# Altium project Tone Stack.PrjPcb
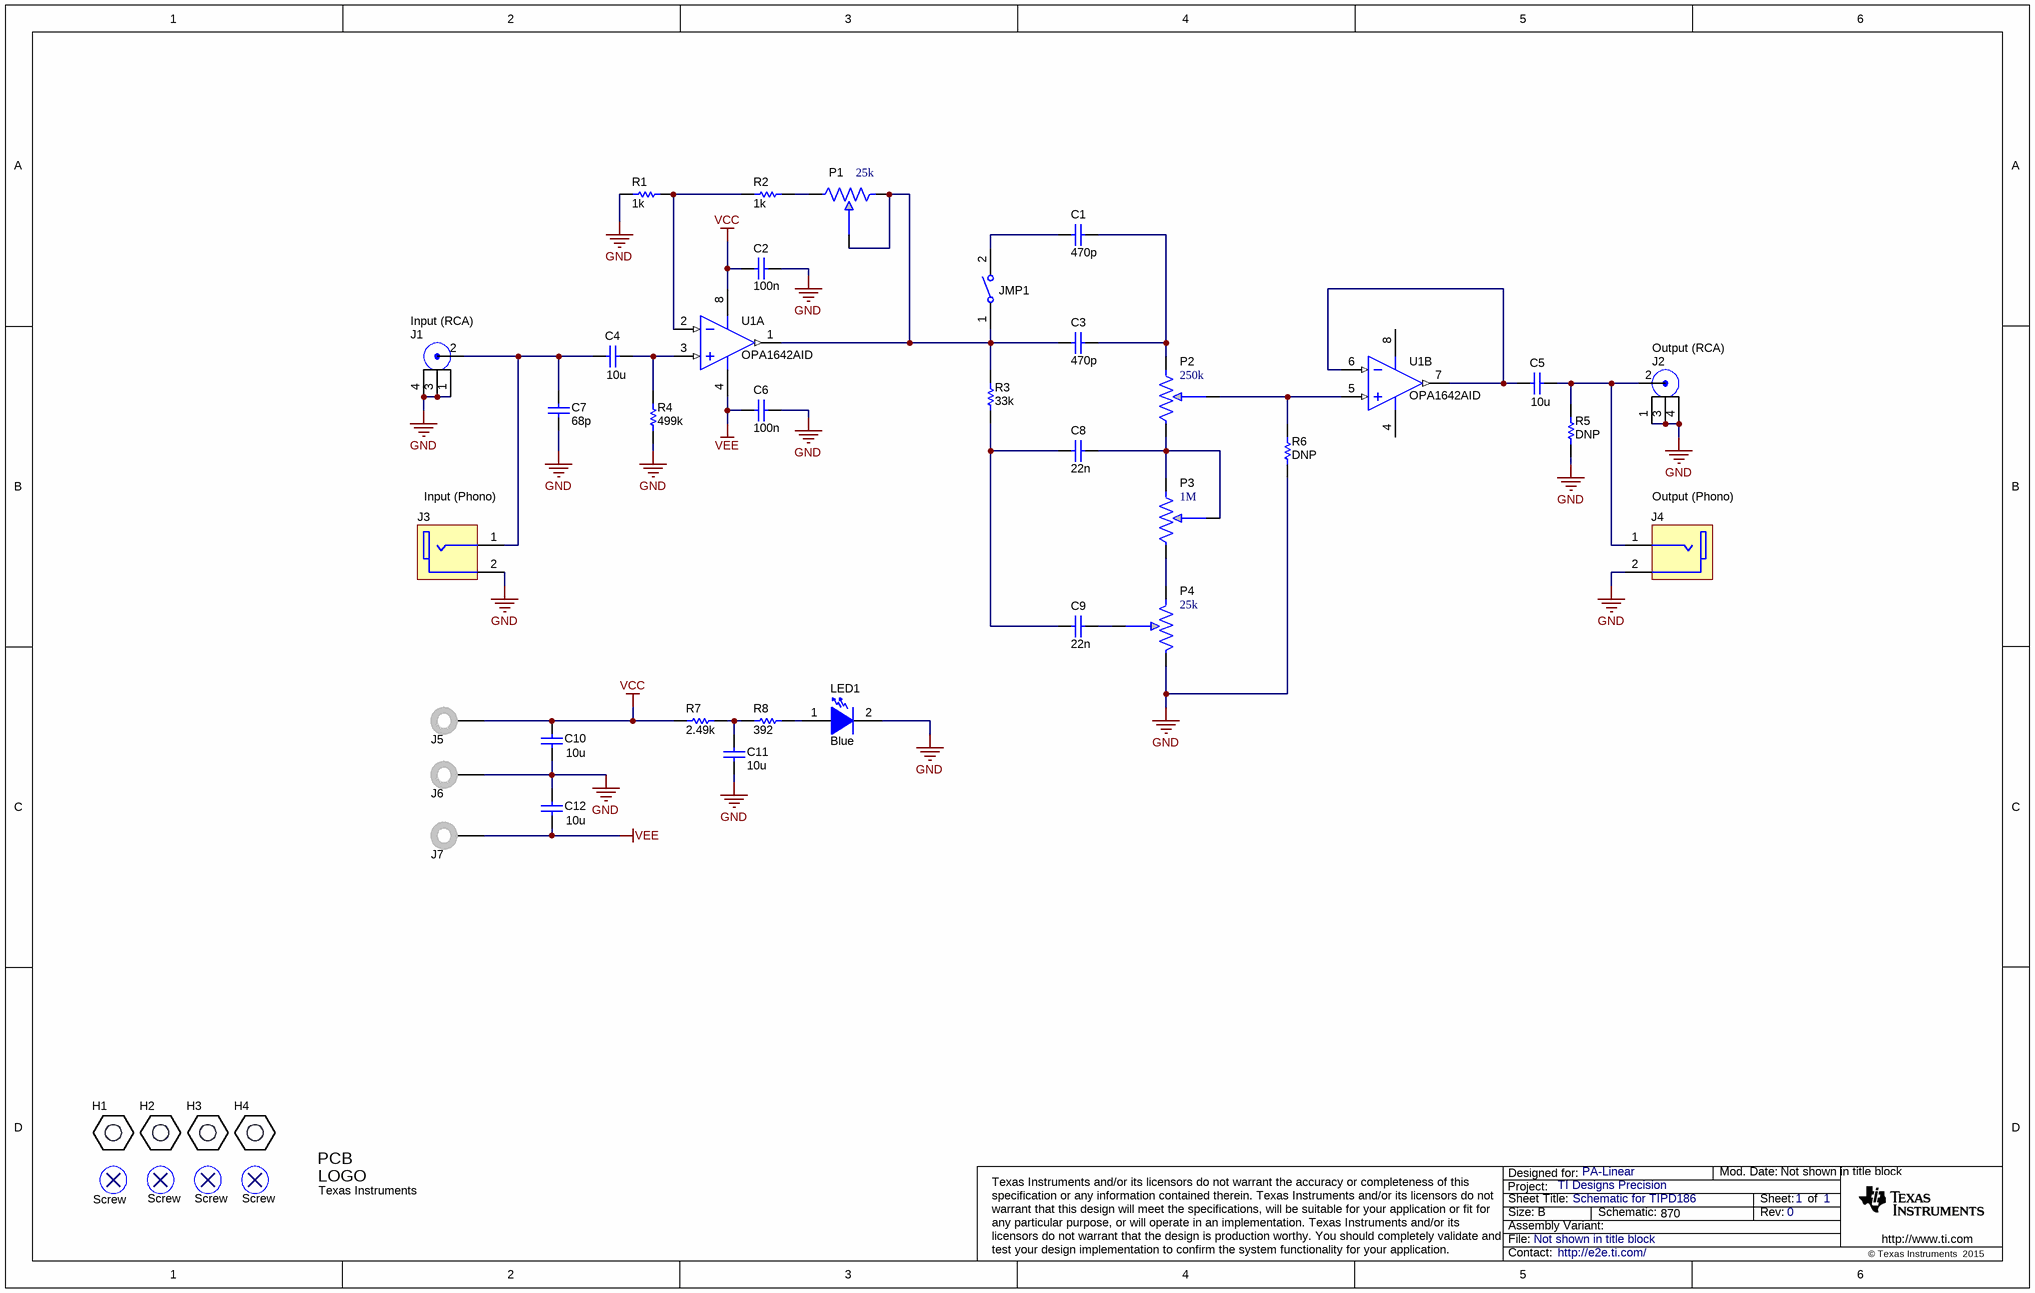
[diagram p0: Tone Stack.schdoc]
TechSupport: http://e2e.ti.com/; SCH_Rev: 0; PRJ_Title: TI Designs Precision; PRJ_Customer: PA-Linear; CopyrightYear: 2015
1 sheet, 43 parts. Net scope: global (net labels, ports and power ports of the same name join across sheets).
Board file: Tone Stack.PcbDoc

## Sheet Tone Stack.schdoc: Schematic for TIPD186
size B; Date: Not shown in title block; ApprovedBy: Not shown in title block; CheckedBy: Not shown in title block; Author: Not shown in title block; CompanyName: Not shown in title block; DrawnBy: Not shown in title block; Engineer: Not shown in title block; Organization: Not shown in title block; Address1: Not shown in title block; Address2: Not shown in title block; Address3: Not shown in title block; Address4: Not shown in title block; DocumentNumber: 1; Revision: Use project parameter SCH_Rev; SheetNumber: 1; SheetTotal: 1; PageSetup: Record=PageOptions|CenterHorizontal=True|CenterVertical=True|PrintScale=0.72|XCorrection=1.00|YCorrection=1.00|PrintKind=0|BorderSize=5000000|LeftOffset=0|BottomOffset=0|Orientation=2|PaperLength=1000|PaperWidth=1000|Scale=100|PaperSource=15|PrintQuality=600|MediaType=1|DitherType=10|PaperKind=Letter|PrintScaleMode=1

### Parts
C1  value 470p  [0603]  (hidden comment: Used in BOM report)
C2  value 100n  [0603]  (hidden comment: Used in BOM report)
C3  value 470p  [0603]  (hidden comment: Used in BOM report)
C4  value 10u  [1206]  (hidden comment: Used in BOM report)
C5  value 10u  [1206]  (hidden comment: Used in BOM report)
C6  value 100n  [0603]  (hidden comment: Used in BOM report)
C7  value 68p  [0603]  (hidden comment: Used in BOM report)
C8  value 22n  [1206]  (hidden comment: Used in BOM report)
C9  value 22n  [1206]  (hidden comment: Used in BOM report)
C10  value 10u  [1206]  (hidden comment: Used in BOM report)
C11  value 10u  [1206]  (hidden comment: Used in BOM report)
C12  value 10u  [1206]  (hidden comment: Used in BOM report)
H1  Standoff, 1", 4-40, Alum, F-F  [STANDOFF HEX 4-40THR ALUM 1"L]  (value not drawn)
H2  Standoff, 1", 4-40, Alum, F-F  [STANDOFF HEX 4-40THR ALUM 1"L]  (value not drawn)
H3  Standoff, 1", 4-40, Alum, F-F  [STANDOFF HEX 4-40THR ALUM 1"L]  (value not drawn)
H4  Standoff, 1", 4-40, Alum, F-F  [STANDOFF HEX 4-40THR ALUM 1"L]  (value not drawn)
J1  Input (RCA)  [RCJ-01X]
J2  Output (RCA)  [RCJ-01X]
J3  Input (Phono)  [Switchcraft_RN111PC]
J4  Output (Phono)  [Switchcraft_RN111PC]
J5  VCC  [JACK NON-INSULATED .218"]  (value not drawn)
J6  GND  [JACK NON-INSULATED .218"]  (value not drawn)
J7  Vee  [JACK NON-INSULATED .218"]  (value not drawn)
JMP1  Mid Boost  [Header 100mil, 1x2]  (value not drawn)
LED1  value Blue  [Header 100mil, 1x2]  (hidden comment: XREBLU-L1-R250-00K01)
Logo1  Texas Instruments  [TI_Stacked_Overlay_Medium]  (no BOM)
P1  value 25k  [POT_RV16]  (hidden comment: Gain)
P2  value 250k  [POT_RV16]  (hidden comment: Treble)
P3  value 1M  [POT_RV16]  (hidden comment: Bass)
P4  value 25k  [POT_RV16]  (hidden comment: Mid)
R1  value 1k  [0603]  (hidden comment: Used in BOM report)
R2  value 1k  [0603]  (hidden comment: Used in BOM report)
R3  value 33k  [0603]  (hidden comment: Used in BOM report)
R4  value 499k  [0603]  (hidden comment: Used in BOM report)
R5  value DNP  [0603]  (hidden comment: Used in BOM report)
R6  value DNP  [0603]  (hidden comment: Used in BOM report)
R7  value 2.49k  [0805]  (hidden comment: Used in BOM report)
R8  value 392  [0805]  (hidden comment: Used in BOM report)
U1  OPA1642AID  [D0008A_N]  (parts A,B of 2)
U2  Screw  (mechanical)
U3  Screw  (mechanical)
U4  Screw  (mechanical)
U5  Screw  (mechanical)

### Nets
GND: C2.2 C6.2 C7.2 C10.2 C11.2 C12.1 J1.1 J1.3 J1.4 J2.1 J2.3 J2.4 J3.2(Tip) J4.2(Tip) J6.1 LED1.2(K) P4.1 R1.2 R4.2 R5.1 R6.1
VCC: C2.1 C10.1 J5.1 R7.1 U1.8(V+)
VEE: C6.1 C12.2 J7.1 U1.4(V-)
NetC1_1: C1.1 JMP1.2
NetC1_2: C1.2 C3.2 P2.3
NetC3_1: C3.1 JMP1.1 P1.2 P1.3 R3.2 U1.1(OUT_A)
NetC4_1: C4.1 R4.1 U1.3(IN_A+)
NetC4_2: C4.2 C7.1 J1.2 J3.1(Sleeve)
NetC5_1: C5.1 J2.2 J4.1(Sleeve) R5.2
NetC5_2: C5.2 U1.6(IN_B-) U1.7(OUT_B)
NetC8_1: C8.1 C9.1 R3.1
NetC8_2: C8.2 P2.1 P3.2 P3.3
NetC9_2: C9.2 P4.2
NetC11_1: C11.1 R7.2 R8.1
NetLED1_1: LED1.1(A) R8.2
NetP1_1: P1.1 R2.1
NetP2_2: P2.2 R6.2 U1.5(IN_B+)
NetP3_1: P3.1 P4.3
NetR1_1: R1.1 R2.2 U1.2(IN_A-)

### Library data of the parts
C1-C12 = Capacitor: CAP, CERM, xxxF, xxV, [TempCo], xx%, [PackageReference]; Polarized: N; U/M: EA
H1-H4 = Standoff, 1", 4-40, Alum, F-F: STANDOFF HEX 4-40THR ALUM 1"L; Manufacturer: Keystone; PartNumber: 2205; SymbolVersion: use current date i.e. 2008-05-20; SymbolCreator: Use LDAP id; CompType: Used in some BOM reports.  Useful for finding later.; U/M: EA, IN, or GM
J1 J2 = RCJ-011: RCA Jack, Metal, Right Angle; Manufacturer: CUI Inc; SymbolVersion: use current date i.e. 2008-05-20; SymbolCreator: Use LDAP id; CompType: Used in some BOM reports.  Useful for finding later.; U/M: EA, IN, or GM
J3 J4 = RN111PC: Phone Jack, 1/4", R/A, TH; Manufacturer: Switchcraft; SymbolCreator: a0411947; CompType: AUDIO JACK; U/M: EA
J5-J7 = Banana Jack, Solder: JACK NON-INSULATED .218"; Manufacturer: Keystone; PartNumber: 575-4; SymbolVersion: use current date i.e. 2008-05-20; SymbolCreator: Use LDAP id; CompType: Used in some BOM reports.  Useful for finding later.; U/M: EA, IN, or GM
JMP1 = CHS-01TB: Switch, Slide, SPST, Top Slide, SMT; Manufacturer: Copal Electronics; SymbolCreator: a0799628; VDC_V: 6; SwitchFunction: Off-On; PositionCount: 1; CurrentRating_mA: 100
LED1 = XREBLU-L1-R250-00K01: LED, Blue, SMD; Manufacturer: Cree; Type: InGaN; Vf_V: 3.3; Value2: 3.3V; Io_A: 0.35; RJC_CperW: 8; Tjmax_C: 150; Power_TotalModule: 1.155; Value1: 1.155W; LambdaD: 470; NumParallelLEDs: 1; LuminousFlux_PhiV: 30.6; Angle: 90; FamilyName: XLamp&#174; XR-E; U/M: EA
Logo1 = TI_Logo: Texas Instrument Corporate Signature; SymbolCreator: a0412235
P1-P4 = POT_CT-9WXXXYYY: Potentiometer, Single Slide,  xxOhms, 0.1W, 20%; Manufacturer: Copal; Area: 100,776
R1-R8 = Resistor: RES, xxx ohm, x%, xW, [PackageReference]; U/M: EA
U1 = OPA1652AID: Sound Plus Low Noise and Distortion, General-Purpose, FET-Input Audio Operational Amplifier, 4.5 to 36 V, -40 to 85 degC, 8-pin SOIC (D0008A), Green (RoHS & no Sb/Br); Manufacturer: Texas Instruments; Alternate Manufacturer: None; Alternate PartNumber: Equivalent; CMRR(Min)(dB): 100; GBW(Typ)(MHz): 18; Iq per channel(Max)(mA): 2.5; Number of Channels: 2; Packing: TUBE; Rating: Catalog; Slew Rate(Typ)(V/us): 10; Sub Family: Audio Operational Amplifier, High Supply Voltage Amplifier (>=30V), Low Noise Amp (<=10nV/rtHz), Precision Amplifier; Total Supply Voltage(Max)(+5V is 5, +/-5V is 10): 36; Total Supply Voltage(Min)(+5V is 5, +/-5V is 10): 4.5; Vio (25C)(Max)(mV): 1.5
U2-U5 = Machine Screw, 4-40, 0.25": MACHINE SCREW PAN PHILLIPS 4-40; Manufacturer: B&F Fastener Supply; PartNumber: PMSSS 440 0025 PH; SymbolVersion: use current date i.e. 2008-05-20; SymbolCreator: Use LDAP id; CompType: Mechanical; U/M: EA, IN, or GM

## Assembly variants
-100A: all parts fitted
